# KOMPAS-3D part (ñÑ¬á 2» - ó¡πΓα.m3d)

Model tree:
1. Эскиз:1
2. Операция выдавливания:1
     Расстояние 1 = 0.6
3. Эскиз:2
4. Вырезать элемент выдавливания:1
     Толщина стенки 1 = 3; Толщина стенки 2 = 3; Расстояние 1 = 10
5. Эскиз:3
6. Вырезать элемент выдавливания:2
     Толщина стенки 1 = 3; Толщина стенки 2 = 3; Расстояние 1 = 10
7. Эскиз:4
8. Вырезать элемент выдавливания:3
     Толщина стенки 1 = 3; Толщина стенки 2 = 3; Расстояние 1 = 10
9. Эскиз:5
10. Вырезать элемент выдавливания:4
     Толщина стенки 1 = 3; Толщина стенки 2 = 3; Расстояние 1 = 10
